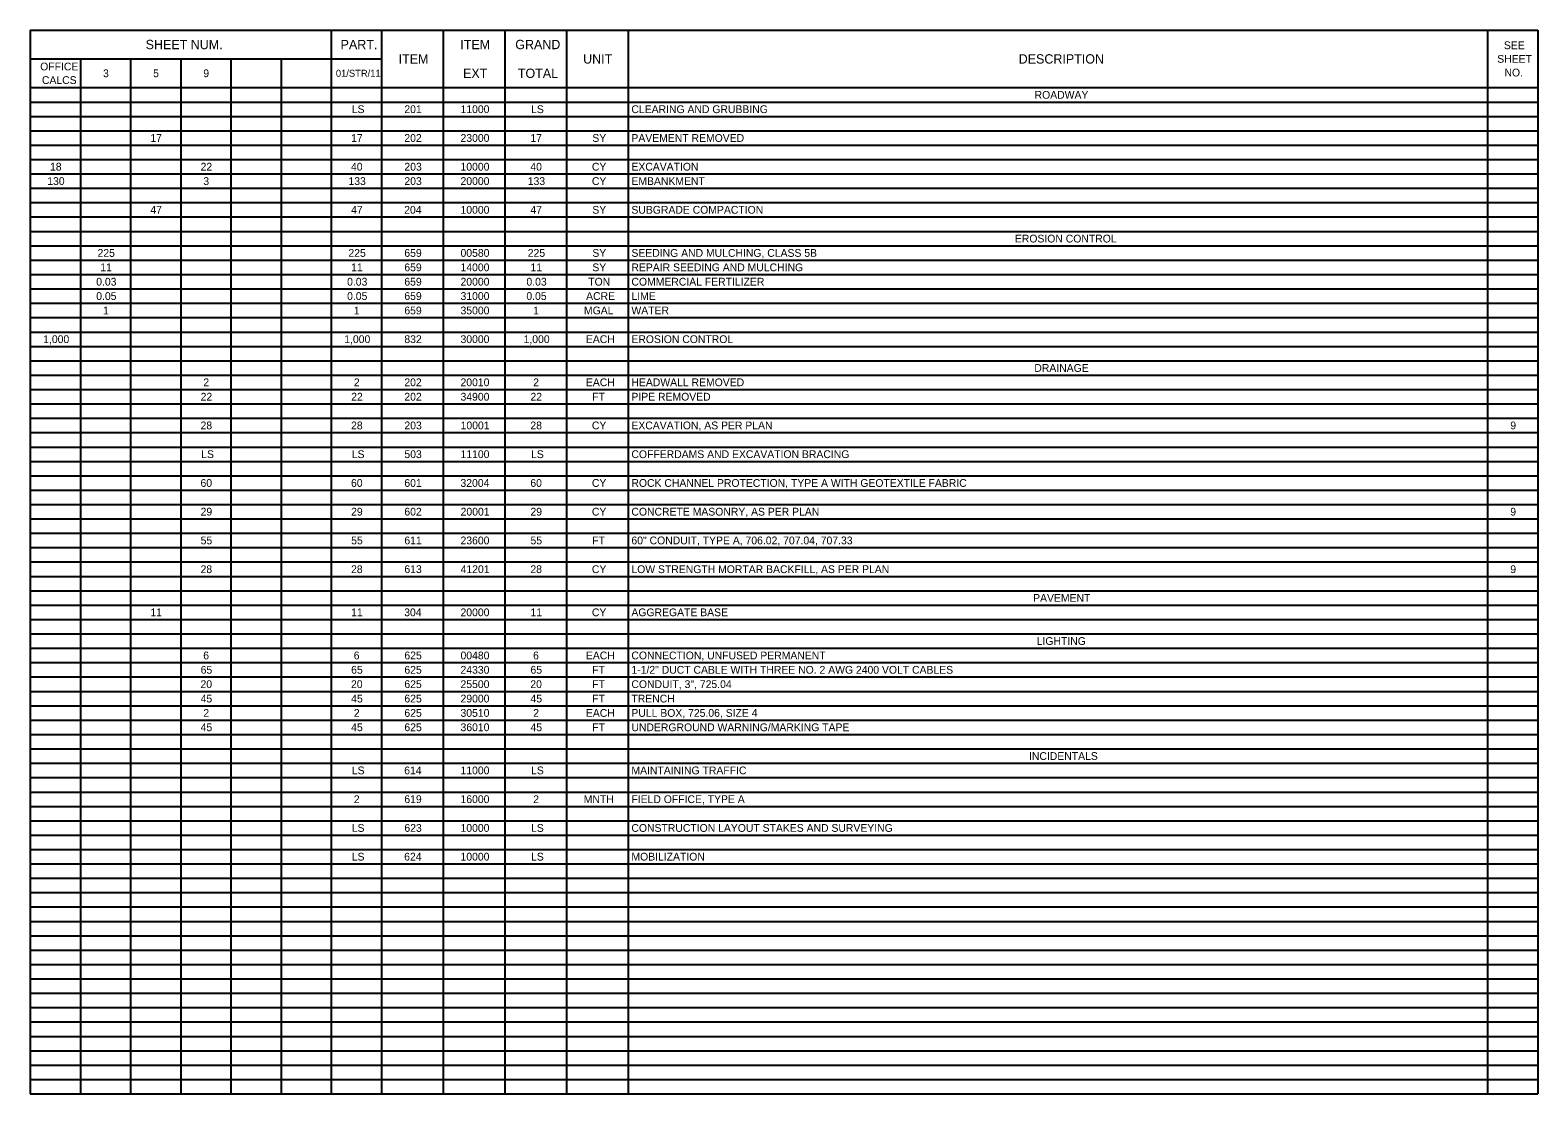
# Model space of a CAD drawing. Extents: x -31.3 to 34, y 0 to 22.
# Drawn here: x -31.25 to -1.54, y 0.53 to 21.5 of the extents above; entities that cross this region are included whole.
import ezdxf

# ---------------------------------------------------------------- set-up
doc = ezdxf.new("R2010")
doc.units = 0
doc.layers.add('SH_Text', color=7, linetype='Continuous')

msp = doc.modelspace()

# ---------------------------------------------------------------- linework, layer by layer
at = {"layer": 'SH_Text'}
for p, q in [((-31.251, 21.5), (-1.539, 21.5)), ((-31.251, 21.5), (-31.251, 0.533)), ((-25.319, 21.5), (-25.319, 0.533)), ((-24.33, 21.5), (-24.33, 0.533)), ((-23.114, 21.5), (-23.114, 0.533)), ((-21.898, 21.5), (-21.898, 0.533)), ((-20.683, 21.5), (-20.683, 0.533)), ((-19.467, 21.5), (-19.467, 0.533)), ((-2.528, 21.5), (-2.528, 0.533)), ((-1.539, 21.5), (-1.539, 0.533)), ((-31.251, 20.933), (-24.33, 20.933)), ((-30.262, 20.933), (-30.262, 0.533)), ((-29.274, 20.933), (-29.274, 0.533)), ((-28.285, 20.933), (-28.285, 0.533)), ((-27.296, 20.933), (-27.296, 0.533)), ((-26.307, 20.933), (-26.307, 0.533)), ((-31.251, 20.367), (-1.539, 20.367)), ((-31.251, 20.083), (-1.539, 20.083)), ((-31.251, 19.8), (-1.539, 19.8)), ((-31.251, 19.517), (-1.539, 19.517)), ((-31.251, 19.233), (-1.539, 19.233)), ((-31.251, 18.95), (-1.539, 18.95)), ((-31.251, 18.667), (-1.539, 18.667)), ((-31.251, 18.383), (-1.539, 18.383)), ((-31.251, 18.1), (-1.539, 18.1)), ((-31.251, 17.817), (-1.539, 17.817)), ((-31.251, 17.533), (-1.539, 17.533)), ((-31.251, 17.25), (-1.539, 17.25)), ((-31.251, 16.967), (-1.539, 16.967)), ((-31.251, 16.683), (-1.539, 16.683)), ((-31.251, 16.4), (-1.539, 16.4)), ((-31.251, 16.117), (-1.539, 16.117)), ((-31.251, 15.833), (-1.539, 15.833)), ((-31.251, 15.55), (-1.539, 15.55)), ((-31.251, 15.267), (-1.539, 15.267)), ((-31.251, 14.983), (-1.539, 14.983)), ((-31.251, 14.7), (-1.539, 14.7)), ((-31.251, 14.417), (-1.539, 14.417)), ((-31.251, 14.133), (-1.539, 14.133)), ((-31.251, 13.85), (-1.539, 13.85)), ((-31.251, 13.567), (-1.539, 13.567)), ((-31.251, 13.283), (-1.539, 13.283)), ((-31.251, 13), (-1.539, 13)), ((-31.251, 12.717), (-1.539, 12.717)), ((-31.251, 12.433), (-1.539, 12.433)), ((-31.251, 12.15), (-1.539, 12.15)), ((-31.251, 11.867), (-1.539, 11.867)), ((-31.251, 11.583), (-1.539, 11.583)), ((-31.251, 11.3), (-1.539, 11.3)), ((-31.251, 11.017), (-1.539, 11.017)), ((-31.251, 10.733), (-1.539, 10.733)), ((-31.251, 10.45), (-1.539, 10.45)), ((-31.251, 10.167), (-1.539, 10.167)), ((-31.251, 9.883), (-1.539, 9.883)), ((-31.251, 9.6), (-1.539, 9.6)), ((-31.251, 9.317), (-1.539, 9.317)), ((-31.251, 9.033), (-1.539, 9.033)), ((-31.251, 8.75), (-1.539, 8.75)), ((-31.251, 8.467), (-1.539, 8.467)), ((-31.251, 8.183), (-1.539, 8.183)), ((-31.251, 7.9), (-1.539, 7.9)), ((-31.251, 7.617), (-1.539, 7.617)), ((-31.251, 7.333), (-1.539, 7.333)), ((-31.251, 7.05), (-1.539, 7.05)), ((-31.251, 6.767), (-1.539, 6.767)), ((-31.251, 6.483), (-1.539, 6.483)), ((-31.251, 6.2), (-1.539, 6.2)), ((-31.251, 5.917), (-1.539, 5.917)), ((-31.251, 5.633), (-1.539, 5.633)), ((-31.251, 5.35), (-1.539, 5.35)), ((-31.251, 5.067), (-1.539, 5.067)), ((-31.251, 4.783), (-1.539, 4.783)), ((-31.251, 4.5), (-1.539, 4.5)), ((-31.251, 4.217), (-1.539, 4.217)), ((-31.251, 3.933), (-1.539, 3.933)), ((-31.251, 3.65), (-1.539, 3.65)), ((-31.251, 3.367), (-1.539, 3.367)), ((-31.251, 3.083), (-1.539, 3.083)), ((-31.251, 2.8), (-1.539, 2.8)), ((-31.251, 2.517), (-1.539, 2.517)), ((-31.251, 2.233), (-1.539, 2.233)), ((-31.251, 1.95), (-1.539, 1.95)), ((-31.251, 1.667), (-1.539, 1.667)), ((-31.251, 1.383), (-1.539, 1.383)), ((-31.251, 1.1), (-1.539, 1.1)), ((-31.251, 0.817), (-1.539, 0.817)), ((-31.251, 0.533), (-1.539, 0.533))]:
    msp.add_line(p, q, dxfattribs=at)

# ---------------------------------------------------------------- texts
for s, height, p in [('SHEET NUM.', 0.184, (-28.975, 21.125)), ('PART.', 0.184, (-25.133, 21.125)), ('ITEM', 0.184, (-22.774, 21.125)), ('GRAND', 0.184, (-21.691, 21.125)), ('SEE ', 0.1533, (-2.208, 21.125)), ('OFFICE ', 0.1533, (-31.053, 20.707)), ('ITEM', 0.184, (-23.989, 20.841)), ('UNIT', 0.184, (-20.354, 20.841)), ('DESCRIPTION', 0.184, (-11.77, 20.841)), ('SHEET ', 0.1533, (-2.339, 20.857)), ('CALCS', 0.1533, (-31.019, 20.439)), ('3', 0.153, (-29.815, 20.573)), ('5', 0.153, (-28.827, 20.573)), ('9', 0.153, (-27.839, 20.573)), ('01/STR/11', 0.138, (-25.226, 20.581)), ('EXT', 0.184, (-22.72, 20.558)), ('TOTAL', 0.184, (-21.64, 20.558)), ('NO.', 0.1533, (-2.197, 20.588)), ('ROADWAY', 0.1533, (-11.456, 20.148)), ('LS', 0.1533, (-24.913, 19.865)), ('201', 0.1533, (-23.877, 19.865)), ('11000', 0.1533, (-22.77, 19.865)), ('LS', 0.1533, (-21.38, 19.865)), ('CLEARING AND GRUBBING', 0.15333, (-19.402, 19.865)), ('17', 0.1533, (-28.882, 19.298)), ('17', 0.1533, (-24.926, 19.298)), ('202', 0.1533, (-23.877, 19.298)), ('23000', 0.1533, (-22.77, 19.298)), ('17', 0.1533, (-21.393, 19.298)), ('SY', 0.1533, (-20.172, 19.298)), ('PAVEMENT REMOVED', 0.15333, (-19.402, 19.298)), ('18', 0.1533, (-30.86, 18.732)), ('22', 0.1533, (-27.892, 18.732)), ('40', 0.1533, (-24.928, 18.732)), ('203', 0.1533, (-23.876, 18.732)), ('10000', 0.1533, (-22.77, 18.732)), ('40', 0.1533, (-21.394, 18.732)), ('CY', 0.1533, (-20.181, 18.732)), ('EXCAVATION', 0.1533, (-19.402, 18.732)), ('130', 0.1533, (-30.914, 18.448)), ('3', 0.153, (-27.838, 18.448)), ('133', 0.1533, (-24.978, 18.448)), ('203', 0.1533, (-23.876, 18.448)), ('20000', 0.1533, (-22.77, 18.448)), ('133', 0.1533, (-21.445, 18.448)), ('CY', 0.1533, (-20.181, 18.448)), ('EMBANKMENT', 0.1533, (-19.402, 18.448)), ('47', 0.1533, (-28.882, 17.882)), ('47', 0.1533, (-24.926, 17.882)), ('204', 0.1533, (-23.88, 17.882)), ('10000', 0.1533, (-22.77, 17.882)), ('47', 0.1533, (-21.393, 17.882)), ('SY', 0.1533, (-20.172, 17.882)), ('SUBGRADE COMPACTION', 0.15333, (-19.402, 17.882)), ('EROSION CONTROL', 0.15333, (-11.845, 17.315)), ('225', 0.1533, (-29.923, 17.032)), ('225', 0.1533, (-24.979, 17.032)), ('659', 0.1533, (-23.877, 17.032)), ('00580', 0.1533, (-22.77, 17.032)), ('225', 0.1533, (-21.445, 17.032)), ('SY', 0.1533, (-20.172, 17.032)), ('SEEDING AND MULCHING, CLASS 5B', 0.15333, (-19.402, 17.032)), ('11', 0.1533, (-29.869, 16.748)), ('11', 0.1533, (-24.926, 16.748)), ('659', 0.1533, (-23.877, 16.748)), ('14000', 0.1533, (-22.77, 16.748)), ('11', 0.1533, (-21.392, 16.748)), ('SY', 0.1533, (-20.172, 16.748)), ('REPAIR SEEDING AND MULCHING', 0.15333, (-19.402, 16.748)), ('0.03', 0.1533, (-29.949, 16.465)), ('0.03', 0.1533, (-25.005, 16.465)), ('659', 0.1533, (-23.877, 16.465)), ('20000', 0.1533, (-22.77, 16.465)), ('0.03', 0.1533, (-21.471, 16.465)), ('TON', 0.1533, (-20.253, 16.465)), ('COMMERCIAL FERTILIZER', 0.15333, (-19.402, 16.465)), ('0.05', 0.1533, (-29.949, 16.182)), ('1', 0.153, (-29.816, 15.898)), ('0.05', 0.1533, (-25.005, 16.182)), ('1', 0.153, (-24.872, 15.898)), ('659', 0.1533, (-23.877, 16.182)), ('659', 0.1533, (-23.877, 15.898)), ('31000', 0.1533, (-22.77, 16.182)), ('35000', 0.1533, (-22.77, 15.898)), ('0.05', 0.1533, (-21.472, 16.182)), ('1', 0.153, (-21.338, 15.898)), ('MGAL', 0.1533, (-20.337, 15.898)), ('ACRE', 0.1533, (-20.295, 16.182)), ('WATER', 0.1533, (-19.402, 15.898)), ('LIME', 0.1533, (-19.402, 16.182)), ('1,000', 0.1533, (-30.994, 15.332)), ('1,000', 0.1533, (-25.061, 15.332)), ('832', 0.1533, (-23.877, 15.332)), ('30000', 0.1533, (-22.77, 15.332)), ('1,000', 0.1533, (-21.527, 15.332)), ('EACH', 0.1533, (-20.299, 15.332)), ('EROSION CONTROL', 0.15333, (-19.402, 15.332)), ('DRAINAGE', 0.1533, (-11.462, 14.765)), ('2', 0.153, (-27.838, 14.482)), ('2', 0.153, (-24.872, 14.482)), ('202', 0.1533, (-23.877, 14.482)), ('20010', 0.1533, (-22.77, 14.482)), ('2', 0.153, (-21.338, 14.482)), ('EACH', 0.1533, (-20.299, 14.482)), ('HEADWALL REMOVED', 0.15333, (-19.402, 14.482)), ('22', 0.1533, (-27.892, 14.198)), ('22', 0.1533, (-24.925, 14.198)), ('202', 0.1533, (-23.877, 14.198)), ('34900', 0.1533, (-22.77, 14.198)), ('22', 0.1533, (-21.392, 14.198)), ('FT', 0.1533, (-20.174, 14.198)), ('PIPE REMOVED', 0.15333, (-19.402, 14.198)), ('28', 0.1533, (-27.893, 13.632)), ('28', 0.1533, (-24.927, 13.632)), ('203', 0.1533, (-23.876, 13.632)), ('10001', 0.1533, (-22.768, 13.632)), ('28', 0.1533, (-21.393, 13.632)), ('CY', 0.1533, (-20.181, 13.632)), ('EXCAVATION, AS PER PLAN', 0.15333, (-19.402, 13.632)), ('9', 0.153, (-2.082, 13.632)), ('LS', 0.1533, (-27.88, 13.065)), ('LS', 0.1533, (-24.913, 13.065)), ('503', 0.1533, (-23.876, 13.065)), ('11100', 0.1533, (-22.77, 13.065)), ('LS', 0.1533, (-21.38, 13.065)), ('COFFERDAMS AND EXCAVATION BRACING', 0.15333, (-19.402, 13.065)), ('60', 0.1533, (-27.894, 12.498)), ('60', 0.1533, (-24.928, 12.498)), ('601', 0.1533, (-23.877, 12.498)), ('32004', 0.1533, (-22.771, 12.498)), ('60', 0.1533, (-21.394, 12.498)), ('CY', 0.1533, (-20.181, 12.498)), ('ROCK CHANNEL PROTECTION, TYPE A WITH GEOTEXTILE FABRIC', 0.15333, (-19.402, 12.498)), ('29', 0.1533, (-27.892, 11.932)), ('29', 0.1533, (-24.926, 11.932)), ('602', 0.1533, (-23.877, 11.932)), ('20001', 0.1533, (-22.768, 11.932)), ('29', 0.1533, (-21.392, 11.932)), ('CY', 0.1533, (-20.181, 11.932)), ('CONCRETE MASONRY, AS PER PLAN', 0.15333, (-19.402, 11.932)), ('9', 0.153, (-2.082, 11.932)), ('55', 0.1533, (-27.891, 11.365)), ('55', 0.1533, (-24.925, 11.365)), ('611', 0.1533, (-23.877, 11.365)), ('23600', 0.1533, (-22.77, 11.365)), ('55', 0.1533, (-21.391, 11.365)), ('FT', 0.1533, (-20.174, 11.365)), ('60" CONDUIT, TYPE A, 706.02, 707.04, 707.33', 0.15333, (-19.402, 11.365)), ('28', 0.1533, (-27.893, 10.798)), ('28', 0.1533, (-24.927, 10.798)), ('613', 0.1533, (-23.876, 10.798)), ('41201', 0.1533, (-22.768, 10.798)), ('28', 0.1533, (-21.393, 10.798)), ('CY', 0.1533, (-20.181, 10.798)), ('LOW STRENGTH MORTAR BACKFILL, AS PER PLAN', 0.15333, (-19.402, 10.798)), ('9', 0.153, (-2.082, 10.798)), ('304', 0.1533, (-23.88, 9.948)), ('20000', 0.1533, (-22.77, 9.948)), ('CY', 0.1533, (-20.181, 9.948)), ('AGGREGATE BASE', 0.15333, (-19.402, 9.948)), ('PAVEMENT', 0.1533, (-11.485, 10.232)), ('11', 0.1533, (-28.881, 9.948)), ('11', 0.1533, (-24.926, 9.948)), ('11', 0.1533, (-21.392, 9.948)), ('LIGHTING', 0.1533, (-11.415, 9.382)), ('6', 0.153, (-27.84, 9.098)), ('6', 0.153, (-24.874, 9.098)), ('625', 0.1533, (-23.876, 9.098)), ('00480', 0.1533, (-22.77, 9.098)), ('6', 0.153, (-21.34, 9.098)), ('EACH', 0.1533, (-20.299, 9.098)), ('CONNECTION, UNFUSED PERMANENT', 0.15333, (-19.402, 9.098)), ('65', 0.1533, (-27.891, 8.815)), ('65', 0.1533, (-24.925, 8.815)), ('625', 0.1533, (-23.876, 8.815)), ('24330', 0.1533, (-22.77, 8.815)), ('65', 0.1533, (-21.391, 8.815)), ('FT', 0.1533, (-20.174, 8.815)), ('1-1/2" DUCT CABLE WITH THREE NO. 2 AWG 2400 VOLT CABLES', 0.15333, (-19.402, 8.815)), ('20', 0.1533, (-27.894, 8.532)), ('20', 0.1533, (-24.928, 8.532)), ('625', 0.1533, (-23.876, 8.532)), ('25500', 0.1533, (-22.77, 8.532)), ('20', 0.1533, (-21.394, 8.532)), ('FT', 0.1533, (-20.174, 8.532)), ('CONDUIT, 3", 725.04', 0.15333, (-19.402, 8.532)), ('45', 0.1533, (-27.891, 8.248)), ('45', 0.1533, (-24.925, 8.248)), ('625', 0.1533, (-23.876, 8.248)), ('29000', 0.1533, (-22.77, 8.248)), ('45', 0.1533, (-21.391, 8.248)), ('FT', 0.1533, (-20.174, 8.248)), ('TRENCH', 0.1533, (-19.402, 8.248)), ('2', 0.153, (-27.838, 7.965)), ('2', 0.153, (-24.872, 7.965)), ('625', 0.1533, (-23.876, 7.965)), ('30510', 0.1533, (-22.77, 7.965)), ('2', 0.153, (-21.338, 7.965)), ('EACH', 0.1533, (-20.299, 7.965)), ('PULL BOX, 725.06, SIZE 4', 0.15333, (-19.402, 7.965)), ('45', 0.1533, (-27.891, 7.682)), ('45', 0.1533, (-24.925, 7.682)), ('625', 0.1533, (-23.876, 7.682)), ('36010', 0.1533, (-22.77, 7.682)), ('45', 0.1533, (-21.391, 7.682)), ('FT', 0.1533, (-20.174, 7.682)), ('UNDERGROUND WARNING/MARKING TAPE', 0.15333, (-19.402, 7.682)), ('INCIDENTALS', 0.15333, (-11.567, 7.115)), ('LS', 0.1533, (-24.913, 6.832)), ('614', 0.1533, (-23.88, 6.832)), ('11000', 0.1533, (-22.77, 6.832)), ('LS', 0.1533, (-21.38, 6.832)), ('MAINTAINING TRAFFIC', 0.15333, (-19.402, 6.832)), ('2', 0.153, (-24.872, 6.265)), ('619', 0.1533, (-23.877, 6.265)), ('16000', 0.1533, (-22.77, 6.265)), ('2', 0.153, (-21.338, 6.265)), ('MNTH', 0.1533, (-20.342, 6.265)), ('FIELD OFFICE, TYPE A', 0.15333, (-19.402, 6.265)), ('LS', 0.1533, (-24.913, 5.698)), ('623', 0.1533, (-23.876, 5.698)), ('10000', 0.1533, (-22.77, 5.698)), ('LS', 0.1533, (-21.38, 5.698)), ('CONSTRUCTION LAYOUT STAKES AND SURVEYING', 0.15333, (-19.402, 5.698)), ('LS', 0.1533, (-24.913, 5.132)), ('624', 0.1533, (-23.88, 5.132)), ('10000', 0.1533, (-22.77, 5.132)), ('LS', 0.1533, (-21.38, 5.132)), ('MOBILIZATION', 0.15333, (-19.402, 5.132))]:
    msp.add_text(s, height=height, dxfattribs=at).set_placement(p)

doc.saveas('drawing.dxf')
